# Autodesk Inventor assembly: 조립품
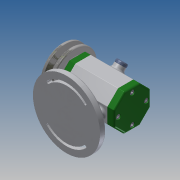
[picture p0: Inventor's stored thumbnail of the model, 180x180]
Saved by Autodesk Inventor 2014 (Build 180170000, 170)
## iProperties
Created: 2017-06
Part Number: 조립품
Document SubType Name: Assembly
Designer: 부인급구
Author: 부인급구
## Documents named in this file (14)
- C:\Users\Administrator\Desktop\470607V1005\조립품.iam
- C:\Users\Administrator\Desktop\470607V1005\470607V1005\본체.ipt
- C:\Users\Administrator\Desktop\470607V1005\470607V1005\V벨트풀리.ipt
- C:\Users\Administrator\Desktop\470607V1005\470607V1005\고무캡.ipt
- C:\Users\Administrator\Desktop\470607V1005\470607V1005\너트 M 8.ipt
- C:\Users\Administrator\Desktop\470607V1005\470607V1005\뒤커버.ipt
- C:\Users\Administrator\Desktop\470607V1005\470607V1005\베어링 15 x 32 x 9.ipt
- C:\Users\Administrator\Desktop\470607V1005\470607V1005\볼트 M4 x 12.ipt
- C:\Users\Administrator\Desktop\470607V1005\470607V1005\스프링와셔 8.ipt
- C:\Users\Administrator\Desktop\470607V1005\470607V1005\앞커버.ipt
- C:\Users\Administrator\Desktop\470607V1005\470607V1005\오일 실 15 25 7.ipt
- C:\Users\Administrator\Desktop\470607V1005\470607V1005\와셔 8x17.ipt
- C:\Users\Administrator\Desktop\470607V1005\470607V1005\축.ipt
- C:\Users\Administrator\Desktop\470607V1005\470607V1005\키 3 x 3 x 12.ipt
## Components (2 placed, 2 different names)
1. V벨트풀리:1
2. 고무캡:1
